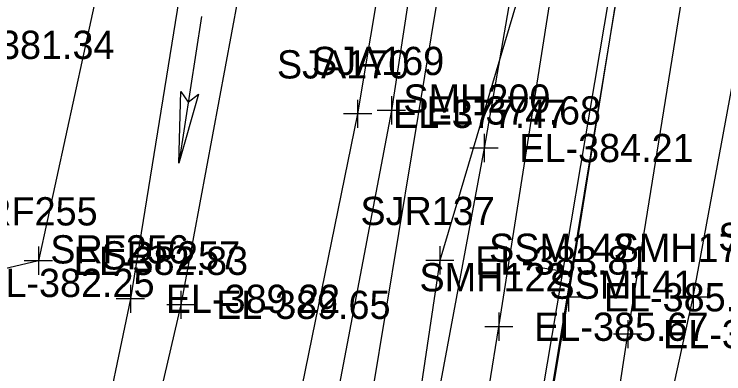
# Model space of a CAD drawing. Extents: x 1189978 to 1314812, y 571533 to 629339.
# Drawn here: x 1217522.9 to 1217623.3, y 621811.9 to 621862.8 of the extents above; entities that cross this region are included whole.
import ezdxf

# ---------------------------------------------------------------- set-up
doc = ezdxf.new("R2010")
doc.units = 0
for name, color, linetype in [('SURVEY - CENTERLINE - Preliminary', 7, 'Continuous'), ('SURVEY - CENTERLINE - Preliminary Text', 7, 'Continuous'), ('SURVEY - DRAINAGE - Area Shapes', 7, 'Continuous'), ('SURVEY - DRAINAGE - Bridge Hydraulic Data with Text', 7, 'Continuous'), ('SURVEY - DTM - Breaklines', 7, 'Continuous'), ('SURVEY - DTM - Breaklines - Points - Elevations', 7, 'Continuous'), ('SURVEY - DTM - Breaklines - Points - Locators', 7, 'Continuous'), ('SURVEY - DTM - Breaklines - Points - Numbers', 7, 'Continuous'), ('SURVEY - PROPERTY - ROW Lines', 7, 'Continuous'), ('SURVEY - TRANSPORTATION - Roads', 7, 'Continuous'), ('SURVEY - TRANSPORTATION - Roads - Points - Elevations', 7, 'Continuous'), ('SURVEY - TRANSPORTATION - Roads - Points - Locators', 7, 'Continuous'), ('SURVEY - TRANSPORTATION - Roads - Points - Numbers', 7, 'Continuous'), ('SURVEY - VEGETATION - Features - Points - Elevations', 7, 'Continuous'), ('SURVEY - VEGETATION - Features - Points - Locators', 7, 'Continuous'), ('SURVEY - VEGETATION - Features - Points - Numbers', 7, 'Continuous'), ('SURVEY - VEGETATION - Features with Text', 7, 'Continuous')]:
    doc.layers.add(name, color=color, linetype=linetype)

msp = doc.modelspace()

# ---------------------------------------------------------------- linework, layer by layer
at = {"layer": 'SURVEY - CENTERLINE - Preliminary'}
msp.add_line((1217525.37, 621363.65), (1217649.69, 622116.55), dxfattribs=at)
msp.add_line((1217525.37, 621363.65), (1217649.69, 622116.55), dxfattribs=at)
at = {"layer": 'SURVEY - CENTERLINE - Preliminary Text'}
msp.add_line((1217601.75, 621826.19), (1217596.81, 621827.01), dxfattribs=at)
at = {"layer": 'SURVEY - DRAINAGE - Area Shapes'}
msp.add_line((1217415.87, 620731.68), (1218149.36, 625079.9), dxfattribs=at)
at = {"layer": 'SURVEY - DRAINAGE - Bridge Hydraulic Data with Text'}
msp.add_line((1217549.36, 621862.49), (1217546.15, 621841.73), dxfattribs=at)
msp.add_lwpolyline([(1217546.15, 621841.73), (1217546.45, 621851.85), (1217547.49, 621850.37), (1217548.97, 621851.46)], close=True, dxfattribs=at)
msp.add_lwpolyline([(1217546.15, 621841.73), (1217546.45, 621851.85), (1217547.49, 621850.37), (1217548.97, 621851.46), (1217546.15, 621841.73)], dxfattribs=at)
at = {"layer": 'SURVEY - DTM - Breaklines'}
for points in [[(1217591.74, 621765.73), (1217601.34, 621822.74), (1217608.84, 621869.52), (1217625.54, 621971.19), (1217634.6, 622026.63), (1217643.17, 622076.74), (1217651.21, 622124.47), (1217659.56, 622173.57), (1217668.17, 622224.78), (1217678.08, 622282.54), (1217688.16, 622340.37), (1217697.26, 622392.62), (1217705.46, 622440.01), (1217714.49, 622490.86), (1217723.28, 622541.33), (1217731.44, 622588.51), (1217739.96, 622637.78), (1217748.52, 622688.04), (1217748.57, 622688.21), (1217756.95, 622738.51)], [(1217681.03, 622529.83), (1217673.16, 622499.61), (1217666.36, 622465.44), (1217655.82, 622419.52), (1217648.28, 622375.91), (1217643.04, 622327.33), (1217632.09, 622280.16), (1217619.71, 622235.27), (1217613.14, 622189.16), (1217602.51, 622145.75), (1217593.94, 622101.94), (1217587.9, 622057.35), (1217577.79, 622010.33), (1217570.45, 621965.56), (1217560.55, 621920.1), (1217546.67, 621868.08), (1217539.32, 621822.52), (1217534.84, 621801.11)], [(1217685.05, 622529.18), (1217678.55, 622499.44), (1217670.66, 622464.16), (1217662, 622418.29), (1217653.65, 622375.31), (1217647.46, 622326.5), (1217637.7, 622278.06), (1217624.97, 622233.51), (1217617.77, 622187.81), (1217609.29, 622147.05), (1217599.66, 622101.36), (1217592.56, 622056.45), (1217583.44, 622007.19), (1217575.28, 621964.22), (1217564.77, 621919.14), (1217554.54, 621865.01), (1217546.46, 621821.67), (1217537.02, 621781.08), (1217528.09, 621784.53), (1217517.71, 621784.08)], [(1217668.55, 622519.09), (1217665.88, 622505.91), (1217655.91, 622467.59), (1217646.62, 622422.12), (1217637.66, 622376.33), (1217630.45, 622330.1), (1217619.94, 622285.29), (1217610.06, 622239.5), (1217600.78, 622197.96), (1217592.86, 622149.6), (1217580.28, 622104.6), (1217573.51, 622060.94), (1217562.45, 622014.24), (1217553.23, 621969.79), (1217544.82, 621922.02), (1217535.21, 621868.88), (1217526.29, 621827.9)], [(1217696.43, 622511.42), (1217690.45, 622501.14), (1217682.75, 622461.47), (1217672.56, 622421.42), (1217668.77, 622381.8), (1217659.15, 622328.76), (1217653.09, 622287.28), (1217639.42, 622228.14), (1217631.31, 622175.39), (1217620.6, 622119.17), (1217610.69, 622074.17), (1217604.05, 622032.34), (1217595.02, 621981.54), (1217586.73, 621935.16), (1217578.82, 621892.7), (1217571.48, 621848.7), (1217561.74, 621801.1), (1217546.07, 621743.68), (1217517.89, 621741.61)], [(1217697.46, 622510.95), (1217695.23, 622500.63), (1217687.54, 622460.4), (1217680.36, 622419.79), (1217673.4, 622382.01), (1217663.19, 622329.29), (1217655.83, 622286.39), (1217645.17, 622227.36), (1217637.36, 622175.23), (1217627.75, 622118.91), (1217619.76, 622071.57), (1217612.88, 622029.47), (1217598.58, 621981.08), (1217592.58, 621934.99), (1217582.82, 621892.2), (1217576.26, 621849.18), (1217566.85, 621799.58), (1217549.42, 621742.26), (1217567.14, 621728.67)], [(1217704.42, 622509.33), (1217700.3, 622496.16), (1217691.81, 622446.34), (1217683.59, 622396.11), (1217675.05, 622345.79), (1217666.22, 622294.23), (1217657.54, 622241.9), (1217648.88, 622192.24), (1217640.73, 622142.53), (1217632.56, 622094.35), (1217625.38, 622048.54), (1217615.19, 621995.99), (1217607.27, 621946.79), (1217598.3, 621895.28), (1217589.38, 621843.86), (1217580.22, 621794.45), (1217573.72, 621781.31), (1217574.43, 621774.4), (1217580.6, 621768.52)], [(1217604.56, 621765.51), (1217608.59, 621775.31), (1217618.98, 621822.73), (1217628.13, 621872.31), (1217636.41, 621920.88), (1217646.75, 621970.08), (1217652.31, 622022.79), (1217663.53, 622069.73), (1217672.49, 622118.54), (1217678.26, 622168.97), (1217683.24, 622219.55), (1217691.94, 622272.25), (1217701.2, 622320.93), (1217709.61, 622368.48), (1217718.57, 622415.45), (1217724.25, 622459.08), (1217730.45, 622491.37), (1217730.86, 622507.08)], [(1217526.29, 621827.9), (1217513.05, 621824.77), (1217488.49, 621823.48), (1217441.24, 621824.34), (1217397.47, 621829.83), (1217345.53, 621832.46), (1217295.63, 621831.2), (1217245.72, 621829.59), (1217196.06, 621848.65), (1217142.73, 621858.18), (1217088.87, 621861), (1217031.95, 621852.21), (1216981.96, 621833.21)]]:
    msp.add_lwpolyline(points, dxfattribs=at)
at = {"layer": 'SURVEY - DTM - Breaklines - Points - Locators'}
for p, q in [((1217571.48, 621850.7), (1217571.48, 621846.7)), ((1217576.26, 621851.18), (1217576.26, 621847.18)), ((1217573.48, 621848.7), (1217569.48, 621848.7)), ((1217578.26, 621849.18), (1217574.26, 621849.18)), ((1217589.38, 621845.86), (1217589.38, 621841.86)), ((1217591.38, 621843.86), (1217587.38, 621843.86)), ((1217526.29, 621829.9), (1217526.29, 621825.9)), ((1217528.29, 621827.9), (1217524.29, 621827.9)), ((1217539.32, 621824.52), (1217539.32, 621820.52)), ((1217601.34, 621824.74), (1217601.34, 621820.74)), ((1217618.98, 621824.73), (1217618.98, 621820.73)), ((1217546.46, 621823.67), (1217546.46, 621819.67)), ((1217541.32, 621822.52), (1217537.32, 621822.52)), ((1217603.34, 621822.74), (1217599.34, 621822.74)), ((1217620.98, 621822.73), (1217616.98, 621822.73)), ((1217548.46, 621821.67), (1217544.46, 621821.67))]:
    msp.add_line(p, q, dxfattribs=at)
at = {"layer": 'SURVEY - PROPERTY - ROW Lines'}
msp.add_line((1217557.72, 621713), (1217625.03, 622120.62), dxfattribs=at)
at = {"layer": 'SURVEY - TRANSPORTATION - Roads'}
for points in [[(1217582.48, 621767.23), (1217583.27, 621767.61), (1217591.48, 621818.57), (1217599.69, 621870.76), (1217607.53, 621920.91), (1217615.95, 621971.91), (1217624.34, 622024.82), (1217633.57, 622076.49), (1217641.88, 622125.54), (1217650.64, 622175.68), (1217659.24, 622225.33), (1217669.03, 622282.56), (1217679.25, 622341.35), (1217687.87, 622391.11), (1217696.47, 622441.53), (1217705.33, 622491.37), (1217713.95, 622541.79), (1217722.13, 622587.98), (1217731.03, 622638.52), (1217739.75, 622690.1), (1217739.95, 622691.24)], [(1217602.44, 621764.03), (1217601.61, 621764.4), (1217609.73, 621817.52), (1217617.85, 621867.88), (1217626.38, 621920.56), (1217634.53, 621969.83), (1217643.58, 622024.64), (1217652.44, 622075.54), (1217660.7, 622123.44), (1217668.82, 622172.59), (1217677.49, 622224.09), (1217697.4, 622338.83), (1217706.31, 622389.43), (1217714.67, 622438.11), (1217723.73, 622488.94), (1217732.47, 622539.47), (1217740.61, 622586), (1217749.34, 622636.23), (1217757.51, 622686.56)]]:
    msp.add_lwpolyline(points, dxfattribs=at)
at = {"layer": 'SURVEY - TRANSPORTATION - Roads - Points - Locators'}
for p, q in [((1217591.48, 621820.57), (1217591.48, 621816.57)), ((1217609.73, 621819.52), (1217609.73, 621815.52)), ((1217593.48, 621818.57), (1217589.48, 621818.57)), ((1217611.73, 621817.52), (1217607.73, 621817.52))]:
    msp.add_line(p, q, dxfattribs=at)
at = {"layer": 'SURVEY - VEGETATION - Features - Points - Locators'}
for p, q in [((1217583.12, 621829.95), (1217583.12, 621825.95)), ((1217585.12, 621827.95), (1217581.12, 621827.95))]:
    msp.add_line(p, q, dxfattribs=at)
at = {"layer": 'SURVEY - VEGETATION - Features with Text'}
msp.add_lwpolyline([(1217702.96, 622509.49), (1217699.51, 622493.95), (1217693.48, 622453.44), (1217687.22, 622414.99), (1217679.9, 622375.82), (1217673.76, 622340.63), (1217665.91, 622295.21), (1217658.91, 622253.42), (1217654.9, 622206.36), (1217645.64, 622163.87), (1217637.41, 622119.23), (1217630.2, 622079.47), (1217625.49, 622037.7), (1217617.96, 622003.15), (1217610.75, 621959.64), (1217601.11, 621912.04), (1217596.35, 621872.4), (1217583.12, 621827.95), (1217575.08, 621774.11)], dxfattribs=at)

# ---------------------------------------------------------------- texts
at = {"layer": 'SURVEY - DTM - Breaklines - Points - Elevations'}
for s, p in [('EL-377.47', (1217576.48, 621846.7)), ('EL-377.68', (1217581.26, 621847.18)), ('EL-384.21', (1217594.38, 621841.86)), ('EL-382.83', (1217531.29, 621825.9)), ('EL-382.25', (1217518.05, 621822.77)), ('EL-389.22', (1217544.32, 621820.52)), ('EL-385.99', (1217606.34, 621820.74)), ('EL-389.65', (1217551.46, 621819.67))]:
    msp.add_text(s, height=4, dxfattribs=at).set_placement(p)
at = {"layer": 'SURVEY - DTM - Breaklines - Points - Numbers'}
for s, p in [('SJA170', (1217560.06, 621853.7)), ('SJA169', (1217565.01, 621854.18)), ('SMH200', (1217577.96, 621848.86)), ('SRF255', (1217515.05, 621832.9)), ('SRF200', (1217622.54, 621829.29)), ('SRF256', (1217527.97, 621827.52)), ('SSM142', (1217590.1, 621827.74)), ('SMH172', (1217607.74, 621827.73)), ('SRF257', (1217535.22, 621826.67))]:
    msp.add_text(s, height=4, dxfattribs=at).set_placement(p)
at = {"layer": 'SURVEY - TRANSPORTATION - Roads - Points - Elevations'}
for s, p in [('EL-385.67', (1217596.48, 621816.57)), ('EL-385.72', (1217614.73, 621815.52))]:
    msp.add_text(s, height=4, dxfattribs=at).set_placement(p)
at = {"layer": 'SURVEY - TRANSPORTATION - Roads - Points - Numbers'}
for s, p in [('SMH122', (1217580.24, 621823.57)), ('SSM141', (1217598.64, 621822.52))]:
    msp.add_text(s, height=4, dxfattribs=at).set_placement(p)
at = {"layer": 'SURVEY - VEGETATION - Features - Points - Elevations'}
for s, p in [('EL-381.34', (1217512.38, 621856.46)), ('EL-383.81', (1217588.12, 621825.95))]:
    msp.add_text(s, height=4, dxfattribs=at).set_placement(p)
at = {"layer": 'SURVEY - VEGETATION - Features - Points - Numbers'}
msp.add_text('SJR137', height=4, dxfattribs=at).set_placement((1217571.88, 621832.95))

doc.saveas('drawing.dxf')
